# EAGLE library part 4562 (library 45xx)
128-bit static SHIFT REGISTER
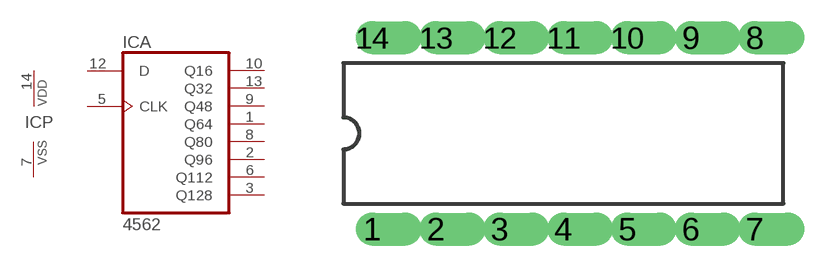
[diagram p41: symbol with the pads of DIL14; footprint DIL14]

Designator prefix IC; gates A=4562 P=PWRN

## 4562N  [DIL14]
1  A:Q64  out
2  A:Q96  out
3  A:Q128  out
5  A:CLK  in
6  A:Q112  out
7  P:VSS  pwr
8  A:Q80  out
9  A:Q48  out
10  A:Q16  out
12  A:D  in
13  A:Q32  out
14  P:VDD  pwr

## Footprint DIL14 (pad centres in mm)
Dual In Line
drill 0.813 offset: 1 -7.62,-3.81; 2 -5.08,-3.81; 3 -2.54,-3.81; 4 0,-3.81; 5 2.54,-3.81; 6 5.08,-3.81; 7 7.62,-3.81; 8 7.62,3.81; 9 5.08,3.81; 10 2.54,3.81; 11 0,3.81; 12 -2.54,3.81; 13 -5.08,3.81; 14 -7.62,3.81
